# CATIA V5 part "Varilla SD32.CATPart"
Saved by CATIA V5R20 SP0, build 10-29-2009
Part number: Varilla SD32
Revision: ANY
Definition: UNKNOWN
Nomenclature: Varilla SD32
Source: Unknown
Bounding box of the stored display mesh (mm): x -5 to 5, y 0 to 180, z -5 to 5
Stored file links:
  C:\Users\Utente\Desktop\IO LAVORO\3D X SITO CF\CUMSA\3D files SD\SD 3220\Varilla SD32.CATPart
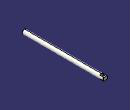
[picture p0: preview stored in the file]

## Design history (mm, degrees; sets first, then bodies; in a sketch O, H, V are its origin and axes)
Body1 "Cortar-Extruir2" (main body)
  Solid1: solid without history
